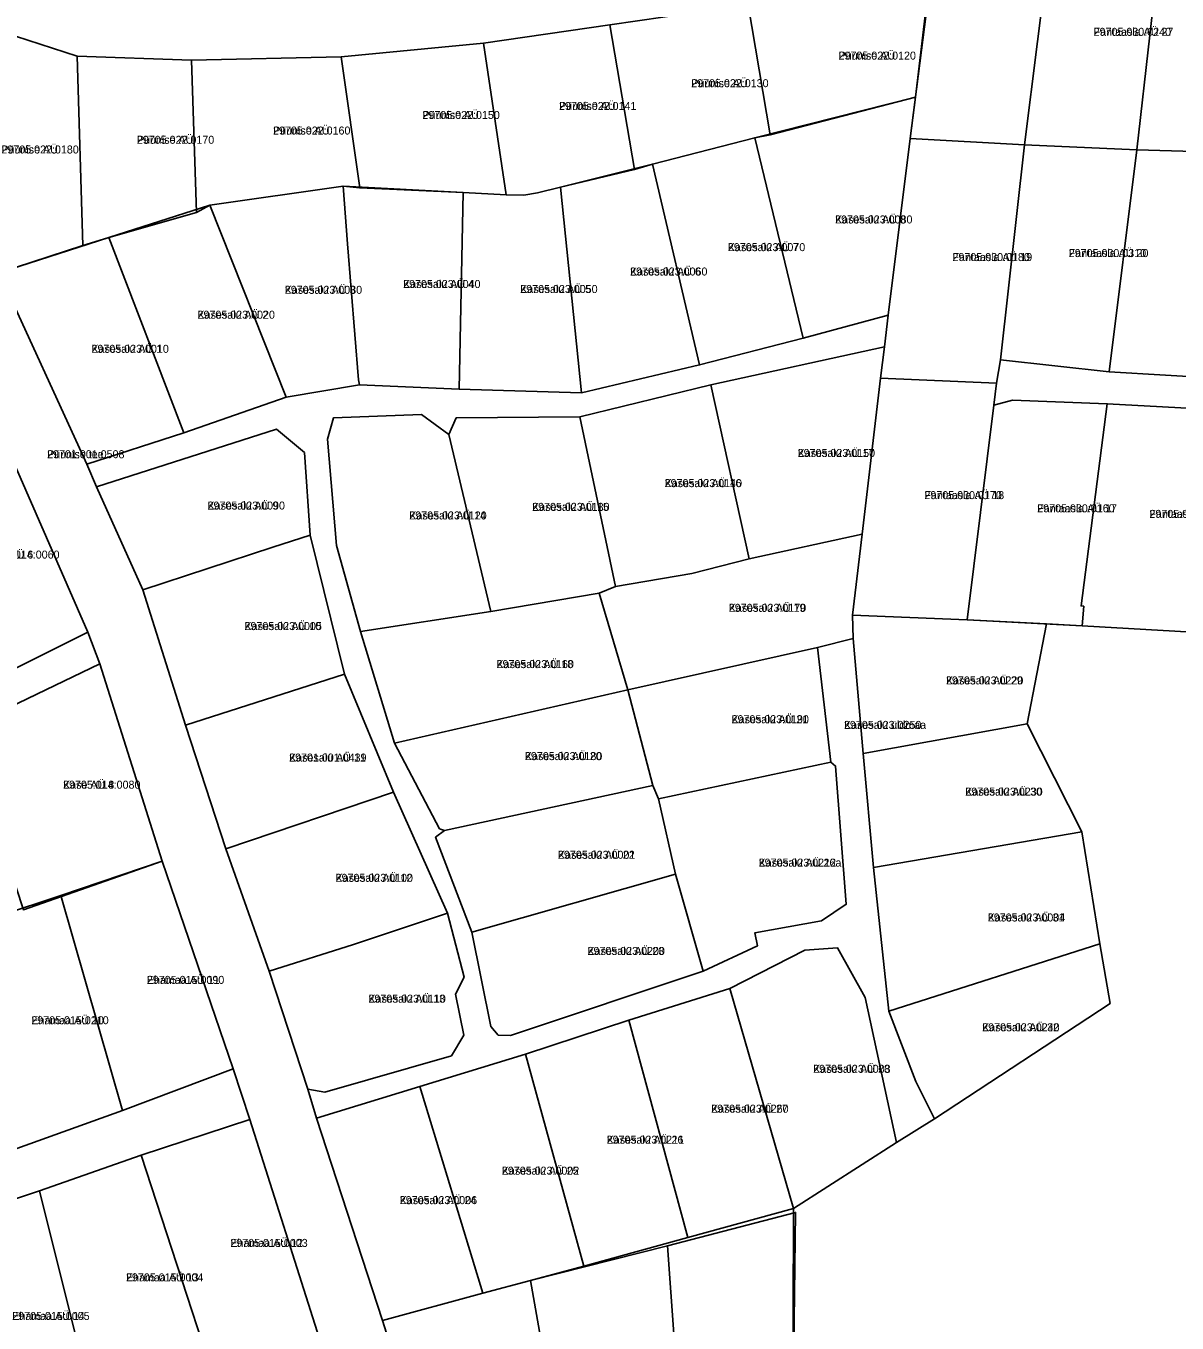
# Model space of a CAD drawing. Extents: x 504287 to 537970, y 6539941 to 6586214.
# Drawn here: x 519486 to 519701.7, y 6563192.6 to 6563435.8 of the extents above; entities that cross this region are included whole.
import ezdxf

# ---------------------------------------------------------------- set-up
doc = ezdxf.new("R2010")
doc.units = 0
for name, color, linetype in [('L_AADRESS', 7, 'Continuous'), ('PIIR', 7, 'Continuous'), ('TUNNUS', 7, 'Continuous')]:
    doc.layers.add(name, color=color, linetype=linetype)

msp = doc.modelspace()

# ---------------------------------------------------------------- linework, layer by layer
at = {"layer": 'PIIR'}
for points in [[(519591.71, 6563035.32), (519588.48, 6563045.08), (519571.99, 6563095.18), (519563.24, 6563121.78), (519555.53, 6563145.56), (519553.5, 6563151.6), (519541.01, 6563189.63), (519527.97, 6563230.8), (519524.82, 6563240.31), (519511.52, 6563279.21), (519499.82, 6563316.19), (519497.57, 6563322.12), (519482.11, 6563357.67), (519469.54, 6563386), (519458.98, 6563403.9), (519434.83, 6563428.79), (519381, 6563460.99)], [(519595.41, 6563435.99), (519571.74, 6563432.58), (519545.04, 6563430.03), (519517.03, 6563429.4), (519495.6, 6563430.16), (519481.71, 6563434.65), (519463.45, 6563444.21)], [(519442.49, 6563436.49), (519445.87, 6563432.43), (519466.1, 6563407.74), (519480.94, 6563389.54), (519497.41, 6563353.65), (519499.23, 6563349.42), (519507.87, 6563330.09), (519515.92, 6563304.72), (519523.48, 6563281.51), (519531.57, 6563258.56), (519538.85, 6563236.49), (519540.44, 6563231.06), (519552.79, 6563193.12), (519562.73, 6563161.59), (519564.41, 6563155.98), (519578.72, 6563112.4), (519590.45, 6563075.98), (519591.52, 6563072.05), (519599.74, 6563045.34), (519653.53, 6562903.18)], [(519709.32, 6563363.83), (519688.63, 6563364.96), (519670.88, 6563365.62), (519667.34, 6563364.73), (519667.85, 6563368.81), (519668.63, 6563373.21), (519689, 6563370.96), (519710.11, 6563369.68)], [(519761.64, 6562908.34), (519628.55, 6563077.91), (519628.67, 6563087.5), (519629.18, 6563128.74), (519629.73, 6563172.82), (519629.86, 6563214.08), (519649.16, 6563226.47), (519656.25, 6563230.91), (519689.16, 6563252.54), (519687.25, 6563263.74), (519683.87, 6563284.73), (519673.62, 6563304.97), (519677.27, 6563323.69), (519683.93, 6563323.34), (519704.56, 6563322.14)], [(519479.81, 6563313.29), (519497.57, 6563322.12), (519499.82, 6563316.19), (519474.38, 6563303.98)], [(519482.74, 6563224.81), (519504.11, 6563232.45), (519524.82, 6563240.31), (519527.97, 6563230.8), (519507.57, 6563224.12), (519488.52, 6563217.41), (519467.92, 6563210.61)]]:
    msp.add_lwpolyline(points, dxfattribs=at)
for points in [[(519657.35, 6563459.07), (519679.45, 6563456.34), (519678, 6563452.29), (519673.1, 6563413.52), (519651.7, 6563414.73)], [(519678, 6563452.29), (519685.48, 6563454.94), (519699.04, 6563455.63), (519694.17, 6563412.56), (519673.1, 6563413.52)], [(519699.04, 6563455.63), (519720.19, 6563454.03), (519715.79, 6563411.98), (519694.17, 6563412.56)], [(519621.31, 6563439.75), (519630.89, 6563441.07), (519655.17, 6563443.62), (519652.68, 6563422.48), (519625.43, 6563415.36)], [(519600.03, 6563408.89), (519595.41, 6563435.99), (519621.31, 6563439.75), (519625.43, 6563415.36), (519622.56, 6563414.84), (519603.4, 6563409.9)], [(519466.1, 6563407.74), (519481.71, 6563434.65), (519495.6, 6563430.16), (519496.67, 6563394.64), (519480.94, 6563389.54)], [(519579.31, 6563404.09), (519576.01, 6563404.15), (519571.74, 6563432.58), (519595.41, 6563435.99), (519600.03, 6563408.89), (519586.19, 6563405.56), (519581.84, 6563404.52)], [(519545.04, 6563430.03), (519571.74, 6563432.58), (519576.01, 6563404.15), (519567.92, 6563404.58), (519548.54, 6563405.42)], [(519496.67, 6563394.64), (519495.6, 6563430.16), (519517.03, 6563429.4), (519517.96, 6563400.84), (519501.52, 6563396.17)], [(519517.96, 6563400.84), (519517.03, 6563429.4), (519545.04, 6563430.03), (519548.54, 6563405.42), (519545.44, 6563405.78), (519520.45, 6563402.17)], [(519622.56, 6563414.84), (519652.68, 6563422.48), (519651.7, 6563414.73), (519647.6, 6563381.55), (519631.66, 6563377.28)], [(519603.4, 6563409.9), (519622.56, 6563414.84), (519631.66, 6563377.28), (519612.22, 6563372.25)], [(519646.87, 6563375.62), (519647.6, 6563381.55), (519651.7, 6563414.73), (519673.1, 6563413.52), (519668.63, 6563373.21), (519667.85, 6563368.81), (519646.14, 6563369.74)], [(519694.17, 6563412.56), (519689, 6563370.96), (519668.63, 6563373.21), (519673.1, 6563413.52)], [(519715.79, 6563411.98), (519710.11, 6563369.68), (519689, 6563370.96), (519694.17, 6563412.56)], [(519586.19, 6563405.56), (519603.4, 6563409.9), (519612.22, 6563372.25), (519590.09, 6563367.02)], [(519520.45, 6563402.17), (519545.44, 6563405.78), (519546.25, 6563394.94), (519548.31, 6563369.46), (519548.52, 6563368.5), (519534.78, 6563366.22)], [(519548.31, 6563369.46), (519546.25, 6563394.94), (519545.44, 6563405.78), (519567.92, 6563404.58), (519567.15, 6563367.71), (519548.52, 6563368.5)], [(519567.92, 6563404.58), (519576.01, 6563404.15), (519579.31, 6563404.09), (519581.84, 6563404.52), (519586.19, 6563405.56), (519590.09, 6563367.02), (519567.15, 6563367.71)], [(519501.52, 6563396.17), (519520.45, 6563402.17), (519534.78, 6563366.22), (519515.6, 6563359.49)], [(519480.94, 6563389.54), (519501.52, 6563396.17), (519515.6, 6563359.49), (519497.41, 6563353.65)], [(519631.96, 6563262.52), (519617.89, 6563255.35), (519598.97, 6563249.39), (519579.59, 6563243.01), (519559.82, 6563236.97), (519540.44, 6563231.06), (519538.85, 6563236.49), (519542.01, 6563235.88), (519565.73, 6563242.71), (519568.08, 6563246.6), (519566.51, 6563254.27), (519568.09, 6563257.48), (519565.01, 6563269.48), (519554.87, 6563292.12), (519545.69, 6563314.27), (519539.23, 6563340.36), (519538.19, 6563355.83), (519532.97, 6563360.18), (519499.23, 6563349.42), (519497.41, 6563353.65), (519515.6, 6563359.49), (519534.78, 6563366.22), (519548.52, 6563368.5), (519567.15, 6563367.71), (519590.09, 6563367.02), (519612.22, 6563372.25), (519631.66, 6563377.28), (519647.6, 6563381.55), (519646.87, 6563375.62), (519614.35, 6563368.52), (519589.81, 6563362.52), (519566.6, 6563362.3), (519565.27, 6563359.21), (519560.09, 6563362.94), (519543.63, 6563362.33), (519542.53, 6563358.32), (519544.22, 6563338.42), (519548.67, 6563322.3), (519555.07, 6563301.34), (519563.51, 6563285.3), (519564.43, 6563284.97), (519562.75, 6563283.69), (519569.58, 6563265.92), (519573.09, 6563248.23), (519574.49, 6563246.57), (519576.81, 6563246.5), (519612.89, 6563258.61), (519623.08, 6563263.31), (519622.56, 6563265.75), (519635.07, 6563268.01), (519639.72, 6563271.13), (519637.73, 6563297.03), (519636.84, 6563297.76), (519634.35, 6563319.28), (519641, 6563320.93), (519642.87, 6563299.37), (519644.83, 6563278.03), (519647.7, 6563251.09), (519652.77, 6563237.9), (519656.25, 6563230.91), (519649.16, 6563226.47), (519643.29, 6563253.67), (519638.1, 6563262.96)], [(519614.35, 6563368.52), (519646.87, 6563375.62), (519646.14, 6563369.74), (519642.68, 6563340.55), (519621.54, 6563335.91)], [(519642.68, 6563340.55), (519646.14, 6563369.74), (519667.85, 6563368.81), (519667.34, 6563364.73), (519662.37, 6563324.47), (519640.87, 6563325.33)], [(519589.81, 6563362.52), (519614.35, 6563368.52), (519621.54, 6563335.91), (519610.76, 6563333.16), (519596.45, 6563330.68)], [(519667.34, 6563364.73), (519670.88, 6563365.62), (519688.63, 6563364.96), (519683.72, 6563327.06), (519684.22, 6563327.02), (519683.93, 6563323.34), (519662.37, 6563324.47)], [(519684.22, 6563327.02), (519683.72, 6563327.06), (519688.63, 6563364.96), (519709.32, 6563363.83), (519704.56, 6563322.14), (519683.93, 6563323.34)], [(519544.22, 6563338.42), (519542.53, 6563358.32), (519543.63, 6563362.33), (519560.09, 6563362.94), (519565.27, 6563359.21), (519573.13, 6563326.03), (519548.67, 6563322.3)], [(519565.27, 6563359.21), (519566.6, 6563362.3), (519589.81, 6563362.52), (519596.45, 6563330.68), (519593.4, 6563329.48), (519573.13, 6563326.03)], [(519499.23, 6563349.42), (519532.97, 6563360.18), (519538.19, 6563355.83), (519539.23, 6563340.36), (519532.29, 6563338.09), (519507.87, 6563330.09)], [(519479.81, 6563313.29), (519478.75, 6563314.65), (519458.01, 6563337.81), (519459.01, 6563344.37), (519461.15, 6563350.34), (519482.11, 6563357.67), (519497.57, 6563322.12)], [(519507.87, 6563330.09), (519532.29, 6563338.09), (519539.23, 6563340.36), (519545.69, 6563314.27), (519515.92, 6563304.72)], [(519642.68, 6563340.55), (519640.87, 6563325.33), (519641, 6563320.93), (519634.35, 6563319.28), (519598.79, 6563311.36), (519593.4, 6563329.48), (519596.45, 6563330.68), (519610.76, 6563333.16), (519621.54, 6563335.91)], [(519548.67, 6563322.3), (519573.13, 6563326.03), (519593.4, 6563329.48), (519598.79, 6563311.36), (519555.07, 6563301.34)], [(519641, 6563320.93), (519640.87, 6563325.33), (519662.37, 6563324.47), (519677.27, 6563323.69), (519673.62, 6563304.97), (519642.87, 6563299.37)], [(519603.5, 6563293.4), (519598.79, 6563311.36), (519634.35, 6563319.28), (519636.84, 6563297.76), (519604.56, 6563290.87)], [(519474.38, 6563303.98), (519499.82, 6563316.19), (519511.52, 6563279.21), (519485.51, 6563270.1)], [(519515.92, 6563304.72), (519545.69, 6563314.27), (519554.87, 6563292.12), (519523.48, 6563281.51)], [(519563.51, 6563285.3), (519555.07, 6563301.34), (519598.79, 6563311.36), (519603.5, 6563293.4), (519564.43, 6563284.97)], [(519642.87, 6563299.37), (519673.62, 6563304.97), (519683.87, 6563284.73), (519644.83, 6563278.03)], [(519623.08, 6563263.31), (519612.89, 6563258.61), (519607.74, 6563276.76), (519604.56, 6563290.87), (519636.84, 6563297.76), (519637.73, 6563297.03), (519639.72, 6563271.13), (519635.07, 6563268.01), (519622.56, 6563265.75)], [(519603.5, 6563293.4), (519604.56, 6563290.87), (519607.74, 6563276.76), (519569.58, 6563265.92), (519562.75, 6563283.69), (519564.43, 6563284.97)], [(519523.48, 6563281.51), (519554.87, 6563292.12), (519565.01, 6563269.48), (519547.38, 6563263.58), (519531.57, 6563258.56)], [(519683.87, 6563284.73), (519687.25, 6563263.74), (519647.7, 6563251.09), (519644.83, 6563278.03)], [(519492.51, 6563272.77), (519511.52, 6563279.21), (519524.82, 6563240.31), (519504.11, 6563232.45)], [(519574.49, 6563246.57), (519573.09, 6563248.23), (519569.58, 6563265.92), (519607.74, 6563276.76), (519612.89, 6563258.61), (519576.81, 6563246.5)], [(519469.89, 6563265.27), (519492.51, 6563272.77), (519504.11, 6563232.45), (519482.74, 6563224.81)], [(519538.85, 6563236.49), (519531.57, 6563258.56), (519547.38, 6563263.58), (519565.01, 6563269.48), (519568.09, 6563257.48), (519566.51, 6563254.27), (519568.08, 6563246.6), (519565.73, 6563242.71), (519542.01, 6563235.88)], [(519631.96, 6563262.52), (519638.1, 6563262.96), (519643.29, 6563253.67), (519649.16, 6563226.47), (519629.86, 6563214.08), (519617.89, 6563255.35)], [(519652.77, 6563237.9), (519647.7, 6563251.09), (519687.25, 6563263.74), (519689.16, 6563252.54), (519656.25, 6563230.91)], [(519598.97, 6563249.39), (519617.89, 6563255.35), (519629.86, 6563214.08), (519610.05, 6563208.65)], [(519579.59, 6563243.01), (519598.97, 6563249.39), (519610.05, 6563208.65), (519590.54, 6563203.29)], [(519559.82, 6563236.97), (519579.59, 6563243.01), (519590.54, 6563203.29), (519580.53, 6563200.62), (519571.63, 6563198.25)], [(519540.44, 6563231.06), (519559.82, 6563236.97), (519571.63, 6563198.25), (519552.79, 6563193.12)], [(519507.57, 6563224.12), (519527.97, 6563230.8), (519541.01, 6563189.63), (519520.95, 6563183.09)], [(519488.52, 6563217.41), (519507.57, 6563224.12), (519520.95, 6563183.09), (519498.93, 6563175.82)], [(519467.92, 6563210.61), (519488.52, 6563217.41), (519498.93, 6563175.82), (519479.59, 6563169.4)], [(519608.79, 6563171.45), (519606.2, 6563207.09), (519630.23, 6563213.35), (519629.73, 6563172.82), (519610.01, 6563168.6)], [(519580.53, 6563200.62), (519606.2, 6563207.09), (519608.79, 6563171.45), (519586.52, 6563166.6)], [(519552.79, 6563193.12), (519571.63, 6563198.25), (519580.53, 6563200.62), (519586.52, 6563166.6), (519562.73, 6563161.59)]]:
    msp.add_lwpolyline(points, close=True, dxfattribs=at)

# ---------------------------------------------------------------- texts
at = {"layer": 'L_AADRESS'}
for s, p in [('Fantaasia AÜ 27', (519686.07, 6563433.95)), ('Püünise AÜ 12', (519638.27, 6563429.49)), ('Püünise AÜ 13', (519610.66, 6563424.32)), ('Püünise AÜ 15', (519560.29, 6563418.36)), ('Püünise AÜ 14', (519585.89, 6563420.05)), ('Püünise AÜ 16', (519532.3, 6563415.44)), ('Püünise AÜ 17', (519506.78, 6563413.71)), ('Püünise AÜ 18', (519481.39, 6563411.89)), ('Kasesalu AÜ 8', (519637.62, 6563398.77)), ('Kasesalu AÜ 7', (519617.53, 6563393.58)), ('Fantaasia AÜ 19', (519659.62, 6563391.72)), ('Fantaasia AÜ 20', (519681.4, 6563392.47)), ('Kasesalu AÜ 6', (519599.2, 6563389.01)), ('Kasesalu AÜ 4', (519556.68, 6563386.67)), ('Kasesalu AÜ 3', (519534.49, 6563385.58)), ('Kasesalu AÜ 5', (519578.62, 6563385.73)), ('Kasesalu AÜ 2', (519518.15, 6563380.91)), ('Kasesalu AÜ 1', (519498.27, 6563374.52)), ('Kasesalu AÜ 17', (519630.61, 6563354.99)), ('Püünise tee', (519489.96, 6563354.76)), ('Kasesalu AÜ 16', (519605.68, 6563349.34)), ('Kasesalu AÜ 9', (519520.03, 6563345.13)), ('Kasesalu AÜ 15', (519580.86, 6563344.89)), ('Fantaasia AÜ 18', (519654.36, 6563347.09)), ('Kasesalu AÜ 14', (519557.83, 6563343.28)), ('Fantaasia AÜ 17', (519675.5, 6563344.62)), ('Fantaasia AÜ 16', (519696.52, 6563343.57)), ('Kase AÜ 6', (519477.79, 6563335.94)), ('Kasesalu AÜ 19', (519617.7, 6563325.96)), ('Kasesalu AÜ 10', (519526.95, 6563322.54)), ('Kasesalu AÜ 18', (519574.18, 6563315.41)), ('Kasesalu AÜ 29', (519658.4, 6563312.35)), ('Kasesalu AÜ 21', (519618.22, 6563305.08)), ('Kasesalu üldmaa', (519639.29, 6563304.01)), ('Kasesalu AÜ 11', (519535.31, 6563297.89)), ('Kasesalu AÜ 20', (519579.5, 6563298.16)), ('Kase AÜ 8', (519492.95, 6563292.8)), ('Kasesalu AÜ 30', (519662.02, 6563291.5)), ('Kasesalu AÜ 22', (519585.69, 6563279.66)), ('Kasesalu AÜ 26a', (519623.3, 6563278.19)), ('Kasesalu AÜ 12', (519544.02, 6563275.34)), ('Kasesalu AÜ 31', (519666.24, 6563267.91)), ('Kasesalu AÜ 23', (519591.23, 6563261.63)), ('Ehamaa AÜ 11', (519508.66, 6563256.21)), ('Kasesalu AÜ 13', (519550.17, 6563252.68)), ('Ehamaa AÜ 10', (519487, 6563248.64)), ('Kasesalu AÜ 32', (519665.19, 6563247.32)), ('Kasesalu AÜ 28', (519633.52, 6563239.53)), ('Kasesalu AÜ 27', (519614.41, 6563232.05)), ('Kasesalu AÜ 26', (519594.82, 6563226.24)), ('Kasesalu AÜ 25', (519575.18, 6563220.43)), ('Kasesalu AÜ 24', (519556.04, 6563214.91)), ('Ehamaa AÜ 12', (519524.29, 6563206.89)), ('Ehamaa AÜ 13', (519504.74, 6563200.43)), ('Ehamaa AÜ 14', (519483.43, 6563193.2))]:
    msp.add_text(s, height=1.5, dxfattribs=at).set_placement(p)
at = {"layer": 'TUNNUS'}
for s, p in [('29705:030:0240', (519686.07, 6563433.95)), ('29705:022:0120', (519638.27, 6563429.49)), ('29705:022:0130', (519610.66, 6563424.32)), ('29705:022:0150', (519560.29, 6563418.36)), ('29705:022:0141', (519585.89, 6563420.05)), ('29705:022:0170', (519506.78, 6563413.71)), ('29705:022:0160', (519532.3, 6563415.44)), ('29705:022:0180', (519481.39, 6563411.89)), ('29705:023:0080', (519637.62, 6563398.77)), ('29705:023:0070', (519617.53, 6563393.58)), ('29705:030:0180', (519659.62, 6563391.72)), ('29705:030:0310', (519681.4, 6563392.47)), ('29705:023:0060', (519599.2, 6563389.01)), ('29705:023:0040', (519556.68, 6563386.67)), ('29705:023:0030', (519534.49, 6563385.58)), ('29705:023:0050', (519578.62, 6563385.73)), ('29705:023:0020', (519518.15, 6563380.91)), ('29705:023:0010', (519498.27, 6563374.52)), ('29705:023:0150', (519630.61, 6563354.99)), ('29701:001:0508', (519489.96, 6563354.76)), ('29705:023:0140', (519605.68, 6563349.34)), ('29705:030:0170', (519654.36, 6563347.09)), ('29705:023:0090', (519520.03, 6563345.13)), ('29705:023:0120', (519557.83, 6563343.28)), ('29705:023:0130', (519580.86, 6563344.89)), ('29705:030:0160', (519675.5, 6563344.62)), ('29705:030:0150', (519696.52, 6563343.57)), ('29705:014:0060', (519477.79, 6563335.94)), ('29705:023:0170', (519617.7, 6563325.96)), ('29705:023:0005', (519526.95, 6563322.54)), ('29705:023:0160', (519574.18, 6563315.41)), ('29705:023:0220', (519658.4, 6563312.35)), ('29705:023:0190', (519618.22, 6563305.08)), ('29705:023:0250', (519639.29, 6563304.01)), ('29701:001:0439', (519535.31, 6563297.89)), ('29705:023:0180', (519579.5, 6563298.16)), ('29705:014:0080', (519492.95, 6563292.8)), ('29705:023:0230', (519662.02, 6563291.5)), ('29705:023:0001', (519585.69, 6563279.66)), ('29705:023:0212', (519623.3, 6563278.19)), ('29705:023:0100', (519544.02, 6563275.34)), ('29705:023:0004', (519666.24, 6563267.91)), ('29705:023:0200', (519591.23, 6563261.63)), ('29705:015:0090', (519508.66, 6563256.21)), ('29705:023:0110', (519550.17, 6563252.68)), ('29705:015:0210', (519487, 6563248.64)), ('29705:023:0240', (519665.19, 6563247.32)), ('29705:023:0003', (519633.52, 6563239.53)), ('29705:023:0260', (519614.41, 6563232.05)), ('29705:023:0211', (519594.82, 6563226.24)), ('29705:023:0002', (519575.18, 6563220.43)), ('29705:023:0006', (519556.04, 6563214.91)), ('29705:015:0003', (519524.29, 6563206.89)), ('29705:015:0004', (519504.74, 6563200.43)), ('29705:015:0005', (519483.43, 6563193.2))]:
    msp.add_text(s, height=1.5, dxfattribs=at).set_placement(p)

doc.saveas('drawing.dxf')
